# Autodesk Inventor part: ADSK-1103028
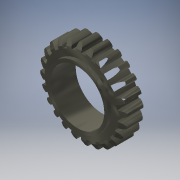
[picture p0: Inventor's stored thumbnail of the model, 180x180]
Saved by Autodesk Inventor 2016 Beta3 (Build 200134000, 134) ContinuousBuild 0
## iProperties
Shininess: 41.0
Length Units: 11272
Angle Units: 11279
Time Units: 11290
Mass Units: 11286
Length Display Precision: 4
Angle Display Precision: 2
Compacted: True
Created: 2000-06
Part Number: ADSK-1103028
Document SubType Name: Modeling
Description: 24 TOOTH CLUTCH GEAR
Mass: 6.16542 g
Surface Area: 11.6587 cm^2
Volume: 0.786406 cm^3
Density: 7.84 g/cm^3
Material: Steel, High Strength Low Alloy
Appearance: Gunmetal
Density: 0.0
Volumn: 0.0
Area: 0.0
PropertySet Name: Model Information
Control State: 0
Master: False
Checked Out: False
Author: Autodesk, Inc.
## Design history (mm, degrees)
node "Extrusion1" dims "d2" = 5.08 (= Thickness), "d3" = 0
  sketch "Sketch2"
    geometry: C1 r 8.607 at (0, 0); 1 further point
    constraints: 1 centre point, 1 coincident
    dimensions: "d0" = 17.21326 diameter of C1 (= RD)
node "Extrusion2" dims "d17" = 6.35, "d18" = 0
  sketch "Sketch3"
    geometry: L1 (0, 0)-(0, 27.478); L2 (0, 9.525)-(-7.278, 9.525); L3 (0, 9.525)-(-4.075, 8.471); L4 (0.054, 9.221)-(0.051, 8.606); L5 (-0.675, 10.297)-(-0.563, 8.588); C1 r 8.607 at (0, 0) reference; A1 r 10.319 centre (0, 0) between (-0.371, 10.312) and (-0.675, 10.297); A2 r 9.525 centre (0, 0) between (0, 9.525) and (-0.623, 9.505); A3 r 9.222 centre (0, 0) between (-2.309, 8.928) and (0.054, 9.221); A4 r 8.607 centre (0, 0) between (0.051, 8.606) and (-0.563, 8.588); A5 r 2.381 centre (-2.309, 8.928) between (0.054, 9.221) and (-0.371, 10.312)
    constraints: 10 end point, 10 point on circle, 5 centre point, 5 point on line, 1 concentric, 1 perpendicular, 1 tangent, 1 vertical
    dimensions: "d4" = 20.6375 diameter of A1 (= OD); "d5" = 19.05 diameter of A2 (= PD); "d6" = 18.44321 diameter of A3 (= BC); "d7" = 17.21326 diameter of A4 (= RD); "d8" = 14.5 deg angle of L2 L3 (= AN); "d9" = 4.7625 diameter of A5 (= 0.25 x PD); "d10" = 0.62309 distance of L2.start A2.end (= 0.5 x CT)
node "Mirror1"
node "Extrusion4" dims "d25" = 0.8636, "d26" = 0
  sketch "Sketch5"
    geometry: C1 r 7.144 at (0, 0); A1 r 10.319 centre (0, 0) between (-4.834, -9.116) and (-4.29, -9.385) reference
    constraints: 1 centre point, 1 coincident
    dimensions: "d30" = 14.2875 diameter of C1
node "Extrusion5" dims "d28" = 5.08, "d29" = 0
  sketch "Sketch6"
    geometry: C1 r 7.144 at (0, 0) reference; C2 r 6.35 at (0, 0)
    constraints: 1 centre point, 1 coincident
    dimensions: "d27" = 12.7 diameter of C2
workaxis "Work Axis2"
workplane "Work Plane2"
  workpoint "Work Point1"
node "Revolution1" dims "d34" = 90 deg
  sketch "Sketch7"
    geometry: L1 (-10.314, -0.864)-(-9.049, -0.864); L2 (-9.049, -0.864)-(-10.319, -1.499); L3 (-10.319, -5.944)-(-9.049, -5.944); L4 (-9.049, -5.944)-(-10.319, -5.309); L5 (0, 1.189)-(0, -7.132) reference; L6 (-10.319, -0.864)-(-10.319, -5.944) reference; L7 (-10.314, -0.864)-(-10.319, -0.864)
    constraints: 10 end point, 2 perpendicular, 2 point on line, 1 equal length, 1 parallel
    dimensions: "d31" = 0.635 distance of L1.start L2.end; "d33" = 0.635 distance from line of L4.end L3 (= d31); "d35" = 1.27 distance from line of L6 L1.end (= 2 x d31)
body "Solid1"
node "Circular Pattern1" dims "d19" = 240 (= NM), "d21" = 360 deg
other parameters: "PD" = 19.05 [user parameter; used in 2 equation terms], "ADD" = 0.79375 [user parameter], "DED" = 0.91837 [user parameter], "CL" = 0.12462 [user parameter], "OD" = 20.6375 [user parameter; used in 1 equation term], "RD" = 17.21326 [user parameter; used in 2 equation terms], "BC" = 18.44321 [user parameter; used in 1 equation term], "CP" = 2.49364 [user parameter], "CT" = 1.24619 [user parameter; used in 1 equation term], "AN" = 14.5 deg [user parameter; used in 1 equation term], "d1" = 36.26326 [user parameter], "Thickness" = 5.08 [user parameter; used in 1 equation term], "d11" = 39.6875 [user parameter], "d12" = 38.1 [user parameter], "d13" = 36.88643 [user parameter], "d14" = 36.26326 [user parameter], "d15" = 14.5 deg [user parameter], "d16" = 1.24619 [user parameter]
